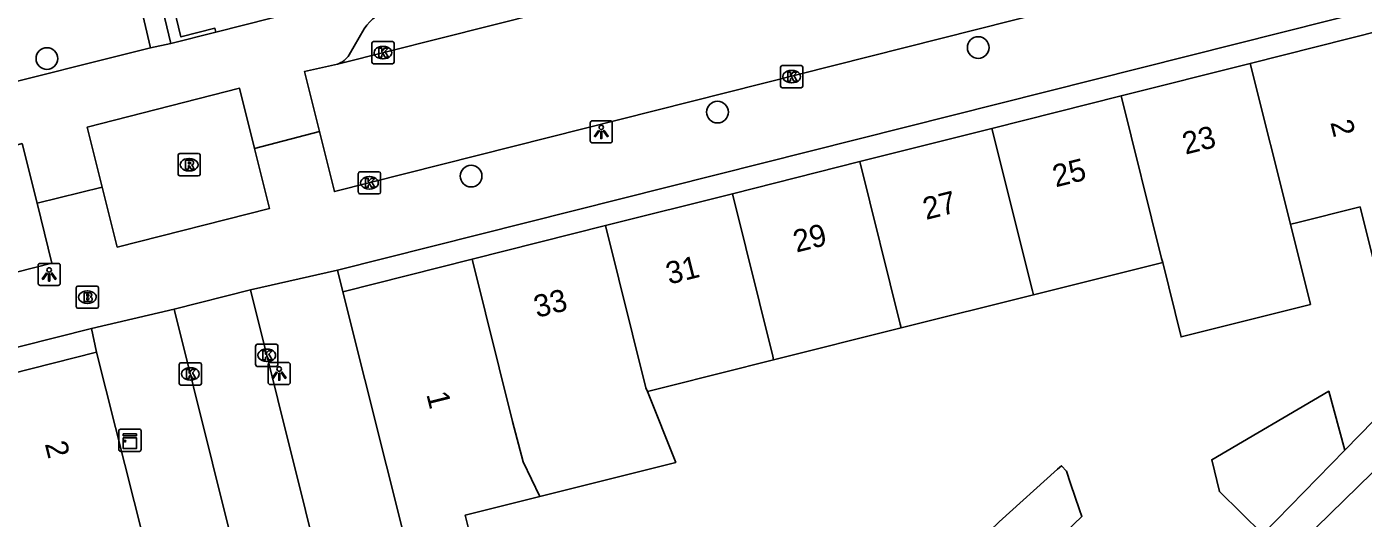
# Model space of a CAD drawing. Extents: x 162532 to 163264, y 381233 to 382042.
# Drawn here: x 162856.2 to 162916.5, y 381707.7 to 381729.9 of the extents above; entities that cross this region are included whole.
import ezdxf

# ---------------------------------------------------------------- set-up
doc = ezdxf.new("R2010")
doc.units = 0
for name, color, linetype in [('IMGEO_Boom', 7, 'Continuous'), ('IMGEO_Brandkraan', 7, 'Continuous'), ('IMGEO_Haag', 7, 'Continuous'), ('IMGEO_Kast', 7, 'Continuous'), ('IMGEO_Kolk', 7, 'Continuous'), ('IMGEO_Lichtpunt', 7, 'Continuous'), ('IMGEO_Pand', 7, 'Continuous'), ('IMGEO_Pand_nummerreeks', 7, 'Continuous'), ('IMGEO_Rijbaan_lokaal_open', 7, 'Continuous'), ('IMGEO_Rioolput', 7, 'Continuous'), ('IMGEO_Voetpad_open', 7, 'Continuous')]:
    doc.layers.add(name, color=color, linetype=linetype)

msp = doc.modelspace()

# ---------------------------------------------------------------- linework, layer by layer
at = {"layer": 'IMGEO_Boom'}
for centre in [(162899.082, 381728.924), (162857.074, 381728.431), (162887.322, 381726.017), (162876.209, 381723.133)]:
    msp.add_circle(centre, 0.489, dxfattribs=at)
at = {"layer": 'IMGEO_Brandkraan'}
for p, q in [((162858.474, 381718.179), (162859.326, 381718.179)), ((162858.399, 381717.253), (162858.399, 381718.105)), ((162858.887, 381717.959), (162858.912, 381717.959)), ((162859.4, 381718.105), (162859.4, 381717.253)), ((162859.326, 381717.179), (162858.474, 381717.179)), ((162858.91, 381717.399), (162858.885, 381717.399))]:
    msp.add_line(p, q, dxfattribs=at)
for points in [[(162858.474, 381718.179), (162859.326, 381718.179)], [(162858.399, 381717.253), (162858.399, 381718.105)], [(162858.747, 381717.879), (162858.747, 381717.479), (162858.96, 381717.479)], [(162858.978, 381717.879), (162858.747, 381717.879)], [(162858.926, 381717.798), (162858.872, 381717.798), (162858.872, 381717.722)], [(162858.872, 381717.722), (162858.925, 381717.722)], [(162858.934, 381717.646), (162858.872, 381717.646), (162858.872, 381717.565)], [(162858.872, 381717.565), (162858.934, 381717.565)], [(162859.4, 381718.105), (162859.4, 381717.253)], [(162859.326, 381717.179), (162858.474, 381717.179)]]:
    msp.add_lwpolyline(points, dxfattribs=at)
for centre, radius, start, end in [((162858.476, 381718.103), 0.0765, 91.55205, 178.44795), ((162858.476, 381718.103), 0.0765, 91.55205, 178.44795), ((162859.324, 381718.103), 0.0765, 1.55205, 88.44795), ((162859.324, 381718.103), 0.0765, 1.55205, 88.44795), ((162858.927, 381717.76), 0.0379, 267.82845, 90.93552), ((162858.935, 381717.605), 0.0404, 269.87594, 90.50774), ((162858.982, 381717.734), 0.145, 59.4692, 91.53667), ((162859.007, 381717.781), 0.0922, 285.51372, 58.15012), ((162859.012, 381717.589), 0.105, 301.31148, 78.98903), ((162858.476, 381717.255), 0.0765, 181.55205, 268.44795), ((162858.476, 381717.255), 0.0765, 181.55205, 268.44795), ((162858.966, 381717.73), 0.251, 268.66757, 293.53466), ((162859.324, 381717.255), 0.0765, 271.55205, 358.44795), ((162859.324, 381717.255), 0.0765, 271.55205, 358.44795)]:
    msp.add_arc(centre, radius, start, end, dxfattribs=at)
for centre, major_axis, ratio, start_param, end_param in [((162858.886, 381717.679), (-0.387, 0.002), 0.722429, 4.712389, 7.853982), ((162858.911, 381717.679), (-0.39, 0.002), 0.717154, 1.570796, 4.712389)]:
    msp.add_ellipse(centre, major_axis=major_axis, ratio=ratio, start_param=start_param, end_param=end_param, dxfattribs=at)
at = {"layer": 'IMGEO_Haag'}
msp.add_lwpolyline([(162864.696, 381729.623), (162864.653, 381729.798), (162863.116, 381729.408), (162862.309, 381732.781), (162862.21, 381733.374), (162861.22, 381737.507), (162860.65, 381739.715), (162859.698, 381743.686), (162859.558, 381744.271), (162858.841, 381747.268), (162860.556, 381747.899), (162860.479, 381748.204)], dxfattribs=at)
at = {"layer": 'IMGEO_Kast'}
for p, q in [((162860.319, 381710.804), (162860.319, 381711.645)), ((162860.319, 381711.645), (162860.319, 381710.804)), ((162860.394, 381711.729), (162861.235, 381711.729)), ((162861.235, 381711.729), (162860.394, 381711.729)), ((162861.319, 381711.654), (162861.319, 381710.813)), ((162861.319, 381710.813), (162861.319, 381711.654)), ((162861.244, 381710.729), (162860.403, 381710.729)), ((162860.403, 381710.729), (162861.244, 381710.729))]:
    msp.add_line(p, q, dxfattribs=at)
for points in [[(162860.514, 381711.519), (162861.114, 381711.519), (162861.114, 381711.434), (162860.514, 381711.434), (162860.514, 381711.519)], [(162860.514, 381711.344), (162861.114, 381711.344), (162861.114, 381710.855), (162860.514, 381710.855), (162860.514, 381711.344)]]:
    msp.add_lwpolyline(points, dxfattribs=at)
msp.add_circle((162860.598, 381711.193), 0.0377, dxfattribs=at)
for centre, start, end in [((162860.397, 381711.651), 92.4484, 184.28452), ((162860.397, 381711.651), 92.4484, 184.28452), ((162861.241, 381711.651), 2.4484, 94.28452), ((162861.241, 381711.651), 2.4484, 94.28452), ((162860.397, 381710.807), 182.4484, 274.28452), ((162860.397, 381710.807), 182.4484, 274.28452), ((162861.241, 381710.807), 272.4484, 4.28452), ((162861.241, 381710.807), 272.4484, 4.28452)]:
    msp.add_arc(centre, 0.0779, start, end, dxfattribs=at)
at = {"layer": 'IMGEO_Kolk'}
for p, q in [((162871.73, 381728.27), (162871.73, 381729.122)), ((162871.805, 381729.196), (162872.657, 381729.196)), ((162872.731, 381729.122), (162872.731, 381728.27)), ((162872.241, 381728.416), (162872.216, 381728.416)), ((162872.218, 381728.976), (162872.243, 381728.976)), ((162872.657, 381728.196), (162871.805, 381728.196)), ((162890.168, 381727.189), (162890.168, 381728.041)), ((162890.243, 381728.115), (162891.095, 381728.115)), ((162890.656, 381727.895), (162890.681, 381727.895)), ((162891.169, 381728.041), (162891.169, 381727.189)), ((162890.679, 381727.335), (162890.654, 381727.335)), ((162891.095, 381727.115), (162890.243, 381727.115)), ((162871.121, 381722.402), (162871.121, 381723.254)), ((162871.196, 381723.328), (162872.048, 381723.328)), ((162871.609, 381723.108), (162871.634, 381723.108)), ((162872.122, 381723.254), (162872.122, 381722.402)), ((162871.632, 381722.548), (162871.607, 381722.548)), ((162872.048, 381722.328), (162871.196, 381722.328)), ((162866.49, 381714.633), (162866.49, 381715.485)), ((162866.565, 381715.559), (162867.417, 381715.559)), ((162866.978, 381715.339), (162867.003, 381715.339)), ((162867.491, 381715.485), (162867.491, 381714.633)), ((162863.043, 381713.793), (162863.043, 381714.645)), ((162863.118, 381714.719), (162863.97, 381714.719)), ((162864.044, 381714.645), (162864.044, 381713.793)), ((162867.417, 381714.559), (162866.565, 381714.559)), ((162867.001, 381714.779), (162866.976, 381714.779)), ((162863.554, 381713.939), (162863.529, 381713.939)), ((162863.531, 381714.499), (162863.556, 381714.499)), ((162863.97, 381713.719), (162863.118, 381713.719))]:
    msp.add_line(p, q, dxfattribs=at)
for points in [[(162871.73, 381728.27), (162871.73, 381729.122)], [(162871.805, 381729.196), (162872.657, 381729.196)], [(162872.731, 381729.122), (162872.731, 381728.27)], [(162872.051, 381728.896), (162872.174, 381728.896), (162872.174, 381728.745), (162872.304, 381728.896), (162872.468, 381728.896), (162872.322, 381728.745), (162872.475, 381728.496), (162872.323, 381728.496), (162872.238, 381728.66), (162872.174, 381728.593), (162872.174, 381728.496), (162872.051, 381728.496), (162872.051, 381728.896)], [(162872.657, 381728.196), (162871.805, 381728.196)], [(162890.168, 381727.189), (162890.168, 381728.041)], [(162890.243, 381728.115), (162891.095, 381728.115)], [(162890.489, 381727.815), (162890.612, 381727.815), (162890.612, 381727.664), (162890.742, 381727.815), (162890.906, 381727.815), (162890.76, 381727.664), (162890.913, 381727.415), (162890.761, 381727.415), (162890.676, 381727.579), (162890.612, 381727.512), (162890.612, 381727.415), (162890.489, 381727.415), (162890.489, 381727.815)], [(162891.169, 381728.041), (162891.169, 381727.189)], [(162891.095, 381727.115), (162890.243, 381727.115)], [(162871.121, 381722.402), (162871.121, 381723.254)], [(162871.196, 381723.328), (162872.048, 381723.328)], [(162871.442, 381723.028), (162871.565, 381723.028), (162871.565, 381722.877), (162871.695, 381723.028), (162871.859, 381723.028), (162871.713, 381722.877), (162871.866, 381722.628), (162871.714, 381722.628), (162871.629, 381722.792), (162871.565, 381722.725), (162871.565, 381722.628), (162871.442, 381722.628), (162871.442, 381723.028)], [(162872.122, 381723.254), (162872.122, 381722.402)], [(162872.048, 381722.328), (162871.196, 381722.328)], [(162866.49, 381714.633), (162866.49, 381715.485)], [(162866.565, 381715.559), (162867.417, 381715.559)], [(162866.811, 381715.259), (162866.934, 381715.259), (162866.934, 381715.108), (162867.064, 381715.259), (162867.228, 381715.259), (162867.082, 381715.108), (162867.235, 381714.859), (162867.083, 381714.859), (162866.998, 381715.023), (162866.934, 381714.956), (162866.934, 381714.859), (162866.811, 381714.859), (162866.811, 381715.259)], [(162867.491, 381715.485), (162867.491, 381714.633)], [(162863.043, 381713.793), (162863.043, 381714.645)], [(162863.118, 381714.719), (162863.97, 381714.719)], [(162864.044, 381714.645), (162864.044, 381713.793)], [(162867.417, 381714.559), (162866.565, 381714.559)], [(162863.364, 381714.419), (162863.487, 381714.419), (162863.487, 381714.268), (162863.617, 381714.419), (162863.781, 381714.419), (162863.635, 381714.268), (162863.788, 381714.019), (162863.636, 381714.019), (162863.551, 381714.183), (162863.487, 381714.116), (162863.487, 381714.019), (162863.364, 381714.019), (162863.364, 381714.419)], [(162863.97, 381713.719), (162863.118, 381713.719)]]:
    msp.add_lwpolyline(points, dxfattribs=at)
for centre, start, end in [((162871.807, 381729.12), 91.55205, 178.44795), ((162871.807, 381729.12), 91.55205, 178.44795), ((162872.655, 381729.12), 1.55205, 88.44795), ((162872.655, 381729.12), 1.55205, 88.44795), ((162871.807, 381728.272), 181.55205, 268.44795), ((162871.807, 381728.272), 181.55205, 268.44795), ((162872.655, 381728.272), 271.55205, 358.44795), ((162872.655, 381728.272), 271.55205, 358.44795), ((162890.245, 381728.039), 91.55205, 178.44795), ((162890.245, 381728.039), 91.55205, 178.44795), ((162891.093, 381728.039), 1.55205, 88.44795), ((162891.093, 381728.039), 1.55205, 88.44795), ((162890.245, 381727.191), 181.55205, 268.44795), ((162890.245, 381727.191), 181.55205, 268.44795), ((162891.093, 381727.191), 271.55205, 358.44795), ((162891.093, 381727.191), 271.55205, 358.44795), ((162871.198, 381723.252), 91.55205, 178.44795), ((162871.198, 381723.252), 91.55205, 178.44795), ((162872.046, 381723.252), 1.55205, 88.44795), ((162872.046, 381723.252), 1.55205, 88.44795), ((162871.198, 381722.404), 181.55205, 268.44795), ((162871.198, 381722.404), 181.55205, 268.44795), ((162872.046, 381722.404), 271.55205, 358.44795), ((162872.046, 381722.404), 271.55205, 358.44795), ((162866.567, 381715.483), 91.55205, 178.44795), ((162866.567, 381715.483), 91.55205, 178.44795), ((162867.415, 381715.483), 1.55205, 88.44795), ((162867.415, 381715.483), 1.55205, 88.44795), ((162863.12, 381714.643), 91.55205, 178.44795), ((162863.12, 381714.643), 91.55205, 178.44795), ((162863.968, 381714.643), 1.55205, 88.44795), ((162863.968, 381714.643), 1.55205, 88.44795), ((162866.567, 381714.635), 181.55205, 268.44795), ((162866.567, 381714.635), 181.55205, 268.44795), ((162867.415, 381714.635), 271.55205, 358.44795), ((162867.415, 381714.635), 271.55205, 358.44795), ((162863.12, 381713.795), 181.55205, 268.44795), ((162863.12, 381713.795), 181.55205, 268.44795), ((162863.968, 381713.795), 271.55205, 358.44795), ((162863.968, 381713.795), 271.55205, 358.44795)]:
    msp.add_arc(centre, 0.0765, start, end, dxfattribs=at)
for centre, major_axis, ratio, start_param, end_param in [((162872.217, 381728.696), (-0.387, 0.002), 0.722429, 4.712389, 7.853982), ((162872.242, 381728.696), (-0.39, 0.002), 0.717154, 1.570796, 4.712389), ((162890.655, 381727.615), (-0.387, 0.002), 0.722429, 4.712389, 7.853982), ((162890.68, 381727.615), (-0.39, 0.002), 0.717154, 1.570796, 4.712389), ((162871.608, 381722.828), (-0.387, 0.002), 0.722429, 4.712389, 7.853982), ((162871.633, 381722.828), (-0.39, 0.002), 0.717154, 1.570796, 4.712389), ((162866.977, 381715.059), (-0.387, 0.002), 0.722429, 4.712389, 7.853982), ((162867.002, 381715.059), (-0.39, 0.002), 0.717154, 1.570796, 4.712389), ((162863.53, 381714.219), (-0.387, 0.002), 0.722429, 4.712389, 7.853982), ((162863.555, 381714.219), (-0.39, 0.002), 0.717154, 1.570796, 4.712389)]:
    msp.add_ellipse(centre, major_axis=major_axis, ratio=ratio, start_param=start_param, end_param=end_param, dxfattribs=at)
at = {"layer": 'IMGEO_Lichtpunt'}
for p, q in [((162881.581, 381725.53), (162881.581, 381724.723)), ((162881.581, 381725.53), (162881.581, 381724.723)), ((162882.483, 381725.625), (162881.675, 381725.625)), ((162882.483, 381725.625), (162881.675, 381725.625)), ((162882.577, 381724.723), (162882.577, 381725.53)), ((162882.577, 381724.723), (162882.577, 381725.53)), ((162881.675, 381724.629), (162882.483, 381724.629)), ((162881.675, 381724.629), (162882.483, 381724.629)), ((162856.676, 381719.107), (162856.676, 381718.3)), ((162856.676, 381719.107), (162856.676, 381718.3)), ((162857.578, 381719.202), (162856.77, 381719.202)), ((162857.578, 381719.202), (162856.77, 381719.202)), ((162857.672, 381718.3), (162857.672, 381719.107)), ((162857.672, 381718.3), (162857.672, 381719.107)), ((162856.77, 381718.206), (162857.578, 381718.206)), ((162856.77, 381718.206), (162857.578, 381718.206)), ((162867.052, 381714.643), (162867.052, 381713.836)), ((162867.052, 381714.643), (162867.052, 381713.836)), ((162867.954, 381714.738), (162867.146, 381714.738)), ((162867.954, 381714.738), (162867.146, 381714.738)), ((162868.048, 381713.836), (162868.048, 381714.643)), ((162868.048, 381713.836), (162868.048, 381714.643)), ((162867.146, 381713.742), (162867.954, 381713.742)), ((162867.146, 381713.742), (162867.954, 381713.742))]:
    msp.add_line(p, q, dxfattribs=at)
for points in [[(162881.955, 381725.194), (162881.994, 381725.166), (162881.806, 381724.904), (162881.768, 381724.931), (162881.955, 381725.194)], [(162882.057, 381725.146), (162882.104, 381725.146), (162882.104, 381724.824), (162882.057, 381724.824), (162882.057, 381725.146)], [(162882.167, 381725.166), (162882.205, 381725.193), (162882.392, 381724.931), (162882.353, 381724.903), (162882.167, 381725.166)], [(162857.05, 381718.771), (162857.089, 381718.743), (162856.901, 381718.481), (162856.863, 381718.508), (162857.05, 381718.771)], [(162857.262, 381718.743), (162857.3, 381718.77), (162857.487, 381718.508), (162857.448, 381718.48), (162857.262, 381718.743)], [(162857.152, 381718.723), (162857.199, 381718.723), (162857.199, 381718.401), (162857.152, 381718.401), (162857.152, 381718.723)], [(162867.426, 381714.307), (162867.465, 381714.279), (162867.277, 381714.017), (162867.239, 381714.044), (162867.426, 381714.307)], [(162867.528, 381714.259), (162867.575, 381714.259), (162867.575, 381713.937), (162867.528, 381713.937), (162867.528, 381714.259)], [(162867.638, 381714.279), (162867.676, 381714.306), (162867.863, 381714.044), (162867.824, 381714.016), (162867.638, 381714.279)]]:
    msp.add_lwpolyline(points, dxfattribs=at)
for centre in [(162882.08, 381725.328), (162857.175, 381718.905), (162867.551, 381714.441)]:
    msp.add_circle(centre, 0.0994, dxfattribs=at)
for centre, start, end in [((162881.675, 381725.53), 90, 180), ((162881.675, 381725.53), 90, 180), ((162882.483, 381725.53), 0, 90), ((162882.483, 381725.53), 0, 90), ((162881.675, 381724.723), 180, 270), ((162881.675, 381724.723), 180, 270), ((162882.483, 381724.723), 270, 0), ((162882.483, 381724.723), 270, 360), ((162856.77, 381719.107), 90, 180), ((162856.77, 381719.107), 90, 180), ((162857.578, 381719.107), 0, 90), ((162857.578, 381719.107), 0, 90), ((162856.77, 381718.3), 180, 270), ((162856.77, 381718.3), 180, 270), ((162857.578, 381718.3), 270, 0), ((162857.578, 381718.3), 270, 360), ((162867.146, 381714.643), 90, 180), ((162867.146, 381714.643), 90, 180), ((162867.954, 381714.643), 0, 90), ((162867.954, 381714.643), 0, 90), ((162867.146, 381713.836), 180, 270), ((162867.146, 381713.836), 180, 270), ((162867.954, 381713.836), 270, 0), ((162867.954, 381713.836), 270, 360)]:
    msp.add_arc(centre, 0.0946, start, end, dxfattribs=at)
at = {"layer": 'IMGEO_Pand'}
for points in [[(162919.351, 381717.651), (162920.254, 381717.88), (162917.303, 381729.707), (162911.356, 381728.212)], [(162905.526, 381726.747), (162911.356, 381728.212)], [(162911.356, 381728.212), (162913.166, 381720.962)], [(162905.526, 381726.747), (162899.698, 381725.282)], [(162907.404, 381719.242), (162907.354, 381719.418), (162905.526, 381726.747)], [(162899.698, 381725.282), (162893.737, 381723.784)], [(162901.574, 381717.783), (162901.525, 381717.957), (162899.698, 381725.282)], [(162887.992, 381722.34), (162893.737, 381723.784)], [(162893.737, 381723.784), (162895.564, 381716.463), (162895.614, 381716.291)], [(162887.992, 381722.34), (162882.273, 381720.902)], [(162889.848, 381714.848), (162889.817, 381715.023), (162887.992, 381722.34)], [(162913.166, 381720.962), (162913.374, 381721.014), (162916.309, 381721.748), (162917.456, 381717.169)], [(162882.273, 381720.902), (162876.255, 381719.389)], [(162884.162, 381713.425), (162884.096, 381713.589), (162882.273, 381720.902)], [(162913.166, 381720.962), (162914.067, 381717.352), (162908.235, 381715.887), (162907.404, 381719.242)], [(162870.429, 381717.925), (162876.255, 381719.389)], [(162876.255, 381719.389), (162878.079, 381712.081), (162878.553, 381710.264), (162879.301, 381708.696)], [(162901.574, 381717.783), (162907.404, 381719.242)], [(162873.378, 381706.128), (162870.429, 381717.925)], [(162895.614, 381716.291), (162901.574, 381717.783)], [(162895.614, 381716.291), (162889.848, 381714.848)], [(162859.316, 381715.205), (162853.436, 381713.713)], [(162859.316, 381715.205), (162862.283, 381703.406), (162863.706, 381697.45)], [(162884.162, 381713.425), (162885.065, 381713.651), (162889.848, 381714.848)], [(162879.301, 381708.696), (162885.438, 381710.232), (162884.162, 381713.425)], [(162915.618, 381710.782), (162914.896, 381713.442), (162909.615, 381710.354), (162909.96, 381708.916), (162911.914, 381707.002)], [(162911.914, 381707.002), (162915.618, 381710.782)], [(162900.518, 381706.07), (162899.503, 381707.076), (162899.602, 381707.165), (162899.875, 381707.411), (162900.033, 381707.554), (162902.664, 381709.928), (162902.836, 381710.083), (162903.06, 381709.835), (162903.252, 381709.277), (162903.655, 381708.098), (162903.761, 381707.789), (162903.014, 381707.092)], [(162879.301, 381708.696), (162875.937, 381707.854), (162876.192, 381706.832), (162873.378, 381706.128)]]:
    msp.add_lwpolyline(points, dxfattribs=at)
at = {"layer": 'IMGEO_Rijbaan_lokaal_open'}
for points in [[(162870.178, 381728.18), (162911.765, 381738.648)], [(162913.701, 381733.445), (162903.836, 381730.962), (162870.042, 381722.432), (162869.37, 381725.142)], [(162869.37, 381725.142), (162868.698, 381727.851), (162870.178, 381728.18)], [(162859.564, 381722.636), (162858.885, 381725.337), (162865.764, 381727.092), (162866.441, 381724.384)], [(162855.209, 381724.395), (162855.433, 381724.451), (162855.955, 381724.6), (162856.627, 381721.906)], [(162866.441, 381724.384), (162867.118, 381721.675), (162860.243, 381719.934), (162859.564, 381722.636)], [(162856.627, 381721.906), (162857.3, 381719.211), (162850.143, 381717.392), (162834.93, 381713.565), (162820.665, 381709.939), (162809.05, 381707.004), (162801.406, 381705.07)], [(162866.25, 381718.01), (162862.821, 381717.136)], [(162866.25, 381718.01), (162869.978, 381703.121)], [(162866.993, 381700.988), (162866.267, 381703.263), (162862.821, 381717.136)]]:
    msp.add_lwpolyline(points, dxfattribs=at)
at = {"layer": 'IMGEO_Rioolput'}
for p, q in [((162862.992, 381723.22), (162862.992, 381724.072)), ((162863.067, 381724.146), (162863.919, 381724.146)), ((162863.48, 381723.926), (162863.505, 381723.926)), ((162863.993, 381724.072), (162863.993, 381723.22)), ((162863.919, 381723.146), (162863.067, 381723.146)), ((162863.503, 381723.366), (162863.478, 381723.366))]:
    msp.add_line(p, q, dxfattribs=at)
for points in [[(162862.992, 381723.22), (162862.992, 381724.072)], [(162863.067, 381724.146), (162863.919, 381724.146)], [(162863.581, 381723.844), (162863.329, 381723.846), (162863.329, 381723.446)], [(162863.329, 381723.446), (162863.453, 381723.446), (162863.453, 381723.608), (162863.464, 381723.608)], [(162863.507, 381723.765), (162863.453, 381723.765), (162863.453, 381723.684)], [(162863.453, 381723.684), (162863.505, 381723.684)], [(162863.511, 381723.579), (162863.582, 381723.446), (162863.722, 381723.446), (162863.657, 381723.572)], [(162863.993, 381724.072), (162863.993, 381723.22)], [(162863.919, 381723.146), (162863.067, 381723.146)]]:
    msp.add_lwpolyline(points, dxfattribs=at)
for centre, radius, start, end in [((162863.069, 381724.07), 0.0765, 91.55205, 178.44795), ((162863.069, 381724.07), 0.0765, 91.55205, 178.44795), ((162863.463, 381723.555), 0.0533, 26.02933, 88.69889), ((162863.489, 381723.873), 0.19, 274.7715, 282.96867), ((162863.513, 381723.669), 0.0964, 77.00612, 93.18647), ((162863.527, 381723.726), 0.0378, 276.66336, 79.67722), ((162863.58, 381723.734), 0.109, 350.36119, 89.41601), ((162863.578, 381723.734), 0.112, 277.58423, 350.98172), ((162863.562, 381723.519), 0.108, 29.51342, 73.79051), ((162863.917, 381724.07), 0.0765, 1.55205, 88.44795), ((162863.917, 381724.07), 0.0765, 1.55205, 88.44795), ((162863.069, 381723.222), 0.0765, 181.55205, 268.44795), ((162863.069, 381723.222), 0.0765, 181.55205, 268.44795), ((162863.917, 381723.222), 0.0765, 271.55205, 358.44795), ((162863.917, 381723.222), 0.0765, 271.55205, 358.44795)]:
    msp.add_arc(centre, radius, start, end, dxfattribs=at)
for centre, major_axis, ratio, start_param, end_param in [((162863.479, 381723.646), (-0.387, 0.002), 0.722429, 4.712389, 7.853982), ((162863.504, 381723.646), (-0.39, 0.002), 0.717154, 1.570796, 4.712389)]:
    msp.add_ellipse(centre, major_axis=major_axis, ratio=ratio, start_param=start_param, end_param=end_param, dxfattribs=at)
at = {"layer": 'IMGEO_Voetpad_open'}
for points in [[(162857.436, 381747.309), (162861.746, 381728.912)], [(162862.665, 381729.114), (162858.248, 381747.54)], [(162869.74, 381730.888), (162864.696, 381729.623)], [(162917.061, 381730.678), (162870.187, 381718.896)], [(162864.696, 381729.623), (162862.665, 381729.114)], [(162870.708, 381728.599), (162871.378, 381729.763)], [(162862.665, 381729.114), (162861.746, 381728.912)], [(162861.746, 381728.912), (162814.181, 381717.01)], [(162866.441, 381724.384), (162869.37, 381725.142)], [(162856.627, 381721.906), (162859.564, 381722.636)], [(162870.187, 381718.896), (162866.25, 381718.01)], [(162870.429, 381717.925), (162870.187, 381718.896)], [(162862.821, 381717.136), (162859.084, 381716.26)], [(162800.493, 381701.494), (162859.084, 381716.26)], [(162859.084, 381716.26), (162859.316, 381715.205)], [(162915.618, 381710.782), (162920.84, 381716.114)], [(162940.489, 381665.977), (162940.247, 381665.714), (162935.068, 381670.907), (162931.003, 381674.983), (162926.937, 381679.06), (162922.871, 381683.137), (162918.805, 381687.213), (162914.74, 381691.29), (162910.674, 381695.366), (162906.404, 381699.649), (162913.691, 381706.689), (162916.857, 381709.762)]]:
    msp.add_lwpolyline(points, dxfattribs=at)
for centre, radius, start, end in [((162873.179, 381728.57), 2.16, 103.57428, 146.48105), ((162869.914, 381729.059), 0.918, 286.73466, 329.92274)]:
    msp.add_arc(centre, radius, start, end, dxfattribs=at)

# ---------------------------------------------------------------- texts
at = {"layer": 'IMGEO_Pand_nummerreeks'}
for s, rotation, p in [('23', 14.11195, (162908.43, 381724.095)), ('2', 284.00861, (162914.959, 381725.553)), ('25', 14.10927, (162902.579, 381722.624)), ('27', 14.10927, (162896.729, 381721.154)), ('29', 14.10927, (162890.879, 381719.683)), ('31', 14.11195, (162885.14, 381718.241)), ('33', 14.11195, (162879.179, 381716.742)), ('1', 284.0351, (162874.182, 381713.305)), ('2', 284.11506, (162856.974, 381711.07))]:
    msp.add_text(s, height=1, rotation=rotation, dxfattribs=at).set_placement(p)

doc.saveas('drawing.dxf')
